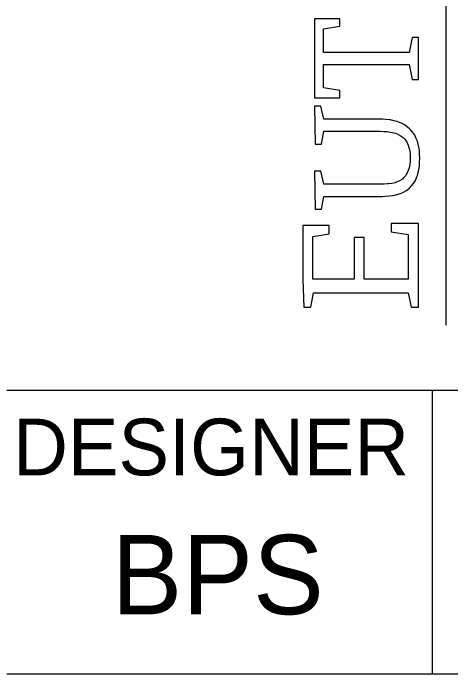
# Model space of a CAD drawing. Extents: x 0 to 34, y 0 to 22.
# Drawn here: x 32.011 to 32.783, y 2.5 to 3.665 of the extents above; entities that cross this region are included whole.
import ezdxf

# ---------------------------------------------------------------- set-up
doc = ezdxf.new("R2010")
doc.units = 0
for name, color, linetype in [('SH_Border', 7, 'Continuous'), ('SH_Data', 7, 'Continuous'), ('SH_Logo', 7, 'Continuous')]:
    doc.layers.add(name, color=color, linetype=linetype)

msp = doc.modelspace()

# ---------------------------------------------------------------- linework, layer by layer
at = {"layer": 'SH_Border'}
for p, q in [((32, 3), (33.5, 3)), ((32.75, 3), (32.75, 2.5)), ((32, 2.5), (33.5, 2.5))]:
    msp.add_line(p, q, dxfattribs=at)
at = {"layer": 'SH_Logo'}
msp.add_line((32.7752, 3.1149), (32.7752, 4.7581), dxfattribs=at)
for points in [[(32.5585, 3.6373), (32.5874, 3.642), (32.5874, 3.6551), (32.5425, 3.6551)], [(32.5585, 3.5747), (32.7099, 3.5747), (32.7147, 3.5484), (32.726, 3.5484), (32.726, 3.6223), (32.7147, 3.6223), (32.7099, 3.596), (32.5585, 3.596)]]:
    msp.add_lwpolyline(points, dxfattribs=at)
for points in [[(32.5585, 3.596), (32.5585, 3.6373), (32.5874, 3.642), (32.5874, 3.6551), (32.5425, 3.6551), (32.5425, 3.5156), (32.5874, 3.5156), (32.5874, 3.5287), (32.5585, 3.5333), (32.5585, 3.5747), (32.7099, 3.5747), (32.7147, 3.5484), (32.726, 3.5484), (32.726, 3.6223), (32.7147, 3.6223), (32.7099, 3.596)], [(32.5585, 3.596), (32.5585, 3.6373), (32.5874, 3.642), (32.5874, 3.6551), (32.5425, 3.6551), (32.5425, 3.5156), (32.5874, 3.5156), (32.5874, 3.5287), (32.5585, 3.5333), (32.5585, 3.5747), (32.7099, 3.5747), (32.7147, 3.5484), (32.726, 3.5484), (32.726, 3.6223), (32.7147, 3.6223), (32.7099, 3.596)], [(32.7116, 3.4095), (32.7114, 3.4048), (32.7108, 3.3983), (32.7097, 3.3926), (32.7081, 3.3877), (32.7063, 3.3834), (32.7032, 3.3782), (32.6994, 3.374), (32.6979, 3.3726), (32.6929, 3.3692), (32.6873, 3.3669), (32.6851, 3.3662), (32.6793, 3.3648), (32.6732, 3.3641), (32.6717, 3.3639), (32.6654, 3.3636), (32.6595, 3.3635), (32.5589, 3.3635), (32.5538, 3.3863), (32.5425, 3.3863), (32.5438, 3.3194), (32.5551, 3.3194), (32.559, 3.3419), (32.6595, 3.3419), (32.6619, 3.342), (32.6678, 3.3422), (32.6745, 3.3428), (32.6803, 3.3435), (32.6862, 3.3448), (32.6923, 3.3464), (32.6944, 3.3471), (32.6998, 3.3495), (32.705, 3.3526), (32.71, 3.3564), (32.71, 3.3565), (32.714, 3.3604), (32.7176, 3.365), (32.7207, 3.3703), (32.7233, 3.3764), (32.7242, 3.3787), (32.7257, 3.3839), (32.7268, 3.3895), (32.7277, 3.3956), (32.7282, 3.4022), (32.7283, 3.4092), (32.7283, 3.4095), (32.7282, 3.4163), (32.7277, 3.4227), (32.7268, 3.4287), (32.7256, 3.4343), (32.7242, 3.4394), (32.7223, 3.4443), (32.7195, 3.4499), (32.7163, 3.4548), (32.7125, 3.4591), (32.7109, 3.4607), (32.7063, 3.4648), (32.7013, 3.4682), (32.696, 3.471), (32.6941, 3.4718), (32.6884, 3.4739), (32.6826, 3.4755), (32.6766, 3.4768), (32.6748, 3.477), (32.6686, 3.4777), (32.6625, 3.4781), (32.6566, 3.4783), (32.5589, 3.4783), (32.5538, 3.5012), (32.5425, 3.5012), (32.5438, 3.4342), (32.5551, 3.4342), (32.5589, 3.4568), (32.6566, 3.4568), (32.6588, 3.4568), (32.6649, 3.4566), (32.671, 3.4562), (32.6739, 3.456), (32.6799, 3.4549), (32.6858, 3.4534), (32.6886, 3.4523), (32.694, 3.4496), (32.6989, 3.446), (32.702, 3.4428), (32.7053, 3.4378), (32.7081, 3.4321), (32.7093, 3.4282), (32.7106, 3.4226), (32.7112, 3.4163)], [(32.5589, 3.3635), (32.5538, 3.3863), (32.5425, 3.3863), (32.5438, 3.3194), (32.5551, 3.3194), (32.559, 3.3419), (32.6595, 3.3419), (32.6619, 3.342), (32.6678, 3.3422), (32.6745, 3.3428), (32.6803, 3.3435), (32.6862, 3.3448), (32.6923, 3.3464), (32.6944, 3.3471), (32.6998, 3.3495), (32.705, 3.3526), (32.71, 3.3564), (32.714, 3.3604), (32.7176, 3.365), (32.7207, 3.3703), (32.7233, 3.3764), (32.7242, 3.3787), (32.7257, 3.3839), (32.7268, 3.3895), (32.7277, 3.3956), (32.7282, 3.4022), (32.7283, 3.4092), (32.7283, 3.4095), (32.7282, 3.4163), (32.7277, 3.4227), (32.7268, 3.4287), (32.7256, 3.4343), (32.7242, 3.4394), (32.7223, 3.4443), (32.7195, 3.4499), (32.7163, 3.4548), (32.7125, 3.4591), (32.7109, 3.4607), (32.7063, 3.4648), (32.7013, 3.4682), (32.696, 3.471), (32.6941, 3.4718), (32.6884, 3.4739), (32.6826, 3.4755), (32.6766, 3.4768), (32.6748, 3.477), (32.6686, 3.4777), (32.6625, 3.4781), (32.6566, 3.4783), (32.5589, 3.4783), (32.5538, 3.5012), (32.5425, 3.5012), (32.5438, 3.4342), (32.5551, 3.4342), (32.5589, 3.4568), (32.6588, 3.4568), (32.6649, 3.4566), (32.671, 3.4562), (32.6739, 3.456), (32.6799, 3.4549), (32.6858, 3.4534), (32.6886, 3.4523), (32.694, 3.4496), (32.6989, 3.446), (32.702, 3.4428), (32.7053, 3.4378), (32.7081, 3.4321), (32.7093, 3.4282), (32.7106, 3.4226), (32.7112, 3.4163), (32.7116, 3.4095), (32.7114, 3.4048), (32.7108, 3.3983), (32.7097, 3.3926), (32.7081, 3.3877), (32.7063, 3.3834), (32.7032, 3.3782), (32.6994, 3.374), (32.6979, 3.3726), (32.6929, 3.3692), (32.6873, 3.3669), (32.6851, 3.3662), (32.6793, 3.3648), (32.6722, 3.3639), (32.6654, 3.3636), (32.6595, 3.3635)], [(32.5361, 3.1467), (32.5406, 3.1718), (32.7081, 3.1718), (32.7134, 3.1467), (32.726, 3.1467), (32.726, 3.2941), (32.6781, 3.2941), (32.6781, 3.2795), (32.7082, 3.275), (32.7082, 3.1958), (32.6305, 3.1958), (32.6305, 3.2693), (32.6129, 3.2693), (32.6129, 3.1958), (32.5399, 3.1958), (32.5399, 3.2714), (32.5683, 3.2761), (32.5683, 3.2906), (32.5221, 3.2906), (32.5221, 3.1954), (32.5236, 3.1467)], [(32.5399, 3.1958), (32.5399, 3.2714), (32.5683, 3.2761), (32.5683, 3.2906), (32.5221, 3.2906), (32.5221, 3.1954), (32.5236, 3.1467), (32.5361, 3.1467), (32.5406, 3.1718), (32.7081, 3.1718), (32.7134, 3.1467), (32.726, 3.1467), (32.726, 3.2941), (32.6781, 3.2941), (32.6781, 3.2795), (32.7082, 3.275), (32.7082, 3.1958), (32.6305, 3.1958), (32.6305, 3.2693), (32.6129, 3.2693), (32.6129, 3.1958)]]:
    msp.add_lwpolyline(points, close=True, dxfattribs=at)

# ---------------------------------------------------------------- texts
at = {"layer": 'SH_Data'}
for s, height, p in [('DESIGNER', 0.1, (32.011, 2.85)), ('BPS', 0.14, (32.1844, 2.605))]:
    msp.add_text(s, height=height, dxfattribs=at).set_placement(p)

doc.saveas('drawing.dxf')
